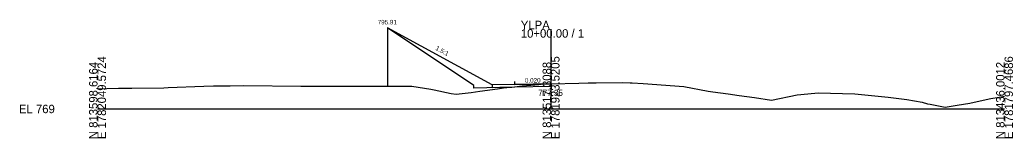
# Model space of a CAD drawing. Extents: x -76 to 1303, y -10 to 9544.
# Drawn here: x -25.7 to 302.8, y -9.7 to 29.6 of the extents above; entities that cross this region are included whole.
import ezdxf

# ---------------------------------------------------------------- set-up
doc = ezdxf.new("R2010")
doc.units = 0
for name, color, linetype in [('Exist Cross Section Cell', 7, 'Continuous'), ('Exist XS Center Line Elevation Label', 7, 'Continuous'), ('Exist XS Ground Line', 7, 'Continuous'), ('Prop XS Ditch Slope Text', 7, 'Continuous'), ('Prop XS Ditch Standard Text', 7, 'Continuous'), ('Prop XS Dump Level', 7, 'Continuous'), ('Prop XS Earthwork Shape', 7, 'Continuous'), ('Prop XS EOT Tick Mark', 7, 'Continuous'), ('Prop XS Finish Grade Earthwork', 7, 'Continuous'), ('Prop XS Finish Grade Paved Shoulder', 7, 'Continuous'), ('Prop XS Finish Grade Pavement', 7, 'Continuous'), ('Prop XS SE Text', 7, 'Continuous'), ('Prop XS Subgrade Earthwork', 7, 'Continuous')]:
    doc.layers.add(name, color=color, linetype=linetype)

msp = doc.modelspace()

# ---------------------------------------------------------------- linework, layer by layer
at = {"layer": 'Exist Cross Section Cell'}
for p, q in [((150, 0), (150, 26.44)), ((0, 0), (150, 0)), ((150, 0), (300, 0))]:
    msp.add_line(p, q, dxfattribs=at)
at = {"layer": 'Exist XS Ground Line'}
for p, q in [((0, 6.69), (3.09, 6.77)), ((3.09, 6.77), (6.98, 6.91)), ((6.98, 6.91), (11.36, 6.94)), ((11.36, 6.94), (21.88, 7.03)), ((21.88, 7.03), (23.37, 7.06)), ((23.37, 7.06), (35.12, 7.54)), ((35.12, 7.54), (38.36, 7.68)), ((38.36, 7.68), (43.85, 7.67)), ((43.85, 7.67), (48.34, 7.74)), ((48.34, 7.74), (67.24, 7.54)), ((67.24, 7.54), (103.99, 7.51)), ((103.99, 7.51), (110.2, 6.56)), ((126.46, 5.85), (132.34, 6.72)), ((132.34, 6.72), (134.96, 7.1)), ((134.96, 7.1), (136.99, 7.28)), ((136.99, 7.28), (140.49, 7.63)), ((140.49, 7.63), (143.36, 7.86)), ((143.36, 7.86), (145.95, 8.13)), ((145.95, 8.13), (146.74, 8.17)), ((146.74, 8.17), (150, 8.35)), ((150, 8.35), (159.23, 8.58)), ((159.23, 8.58), (162.23, 8.65)), ((162.23, 8.65), (164.95, 8.69)), ((164.95, 8.69), (173.49, 8.81)), ((173.49, 8.81), (176.12, 8.69)), ((176.12, 8.69), (176.86, 8.65)), ((176.86, 8.65), (180.46, 8.39)), ((180.46, 8.39), (193.92, 7.42)), ((193.92, 7.42), (201.92, 5.95)), ((110.2, 6.56), (111.32, 6.37)), ((111.32, 6.37), (116.91, 5.15)), ((116.91, 5.15), (118.6, 4.87)), ((118.6, 4.87), (123.58, 5.48)), ((123.58, 5.48), (126.46, 5.85)), ((201.92, 5.95), (203.56, 5.69)), ((203.56, 5.69), (208.56, 5)), ((208.56, 5), (212.24, 4.49)), ((212.24, 4.49), (217.25, 3.79)), ((217.25, 3.79), (222.88, 2.9)), ((222.88, 2.9), (231.46, 4.64)), ((231.46, 4.64), (234.88, 5.01)), ((234.88, 5.01), (238.31, 5.36)), ((238.31, 5.36), (250.53, 4.97)), ((250.53, 4.97), (261.56, 3.94)), ((261.56, 3.94), (267.64, 3.19)), ((293.88, 3.12), (295.5, 3.48)), ((295.5, 3.48), (298.27, 3.96)), ((298.27, 3.96), (300, 4.27)), ((267.64, 3.19), (272.7, 2.28)), ((272.7, 2.28), (274.48, 1.73)), ((274.48, 1.73), (275.37, 1.64)), ((275.37, 1.64), (280.4, 0.61)), ((280.4, 0.61), (284.38, 1.29)), ((284.38, 1.29), (288.56, 1.95)), ((288.56, 1.95), (293.88, 3.12))]:
    msp.add_line(p, q, dxfattribs=at)
at = {"layer": 'Prop XS Dump Level'}
msp.add_line((150, 8.35), (138, 8.1), dxfattribs=at)
at = {"layer": 'Prop XS Earthwork Shape'}
for points in [[(135.43, 7.14), (133.06, 7.09), (124.5, 6.92), (124.5, 7.83), (95.89, 26.91), (95.89, 7.51), (103.99, 7.51), (110.2, 6.56), (111.32, 6.37), (116.91, 5.15), (118.6, 4.87), (123.58, 5.48), (126.46, 5.85), (132.34, 6.72), (134.96, 7.1)], [(135.43, 7.14), (136.99, 7.28), (140.49, 7.63), (143.36, 7.86), (145.95, 8.13), (146.74, 8.17), (150, 8.35), (150, 7.43), (138.02, 7.19)]]:
    msp.add_lwpolyline(points, close=True, dxfattribs=at)
at = {"layer": 'Prop XS EOT Tick Mark'}
for p, q in [((138, 8.1), (138, 9.1)), ((150, 8.35), (150, 9.35))]:
    msp.add_line(p, q, dxfattribs=at)
at = {"layer": 'Prop XS Finish Grade Earthwork'}
for p, q in [((130.5, 7.95), (95.89, 26.91)), ((95.89, 26.91), (95.89, 7.51))]:
    msp.add_line(p, q, dxfattribs=at)
at = {"layer": 'Prop XS Finish Grade Paved Shoulder'}
msp.add_line((138, 8.1), (130.5, 7.95), dxfattribs=at)
at = {"layer": 'Prop XS Finish Grade Pavement'}
msp.add_line((138, 8.1), (150, 8.35), dxfattribs=at)
at = {"layer": 'Prop XS Subgrade Earthwork'}
for p, q in [((130.5, 7.95), (130.5, 7.04)), ((133.06, 7.09), (130.5, 7.04)), ((138.02, 7.19), (133.06, 7.09)), ((150, 7.43), (138.02, 7.19)), ((150, 7.43), (150, 8.35))]:
    msp.add_line(p, q, dxfattribs=at)

# ---------------------------------------------------------------- texts
at = {"layer": 'Exist Cross Section Cell'}
for s, p in [('YLPA', (140, 26.44)), ('10+00.00 / 1', (140, 23.64)), ('EL 769', (-26, -1.4))]:
    msp.add_text(s, height=2.8, dxfattribs=at).set_placement(p)
for s, p in [('E 1782049.5724', (2.8, -10)), ('E 1781923.5205', (152.8, -10)), ('E 1781797.4686', (302.8, -10)), ('N 813598.6164', (0, -10)), ('N 813517.3088', (150, -10)), ('N 813436.0012', (300, -10))]:
    msp.add_text(s, height=2.8, rotation=90, dxfattribs=at).set_placement(p)
at = {"layer": 'Exist XS Center Line Elevation Label'}
msp.add_text('777.35', height=2, dxfattribs=at).set_placement((145.74, 4.35))
at = {"layer": 'Prop XS Ditch Slope Text'}
msp.add_text('1.5:1', height=1.5, rotation=331.2934, dxfattribs=at).set_placement((111.63, 19.69))
at = {"layer": 'Prop XS Ditch Standard Text'}
msp.add_text('795.91', height=1.5, dxfattribs=at).set_placement((92.67, 28.04))
at = {"layer": 'Prop XS SE Text'}
msp.add_text('0.020', height=1.5, rotation=1.1458, dxfattribs=at).set_placement((141.38, 8.67))

doc.saveas('drawing.dxf')
